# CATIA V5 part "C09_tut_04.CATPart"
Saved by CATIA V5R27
Part number: Part1
Bounding box of the stored display mesh (mm): x -112.5 to 112.5, y -202.5 to 80, z -202.5 to 85
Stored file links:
  E:\_Deepak\2017_Deepak\CATIA\Resources\Tutorial Files\Tutorials\c09_catia_v5_6r2016_tut\C09_tut_04.CATPart
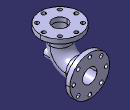
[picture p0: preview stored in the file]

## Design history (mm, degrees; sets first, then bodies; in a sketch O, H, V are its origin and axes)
Body1 (main body)
  Sketch1 on yz-plane, origin (0, 0, 0), H (0, 1, 0), V (0, 0, 1)
    line L1 (-90, 60) -> (-90, 0)
    point P1 (-90, 60)
    arc A1 centre (0, 0) radius 90 from (-90, 0) to (0, -90) ccw
    point P3 (0, 0)
    line L2 (0, -90) -> (55, -90)
    point P5 (55, -90)
    distance P1 L2 = 150
    distance P5 L1 = 145
    radius A1 = 90
    vertical: L1 V
    tangency: A1 L1, L2 A1
    horizontal: L2 H
    coincidence: P3 O
  Plane1: type Normal, Curve Sketch1, RefPoint Sketch1.P5, Ratio 0
  Sketch2 on Plane1, origin (0, 55, 0), H (-1, 0, 0), V (0, 0, 1)
    circle A1 centre (0, -90) radius 48.5
    point P1 (0, -90)
    reference projected point E1 (0, -90) from Sketch1.P5
    radius A1 = 48.5
    coincidence: P1 V, P1 E1
  Rib1: profile Sketch2, centre curve Sketch1, thin wall 16
  Sketch3 on face of Rib1, origin (0, 55, 0), H (-1, 0, 0), V (0, 0, 1)
    circle A1 centre (0, -90) radius 112.5
    point P1 (0, -90)
    reference projected circle E1 centre (0, -90) radius 56.5 from edge [face of Rib1 | face of Rib1]
    circle A2 centre (0, -90) radius 40.5
    reference projected circle E2 centre (0, -90) radius 40.5 from edge [face of Rib1 | face of Rib1]
    radius A1 = 112.5
    coincidence: P1 V, A2 E2
    concentricity: A1 E1
  Pad1: profile Sketch3, direction (0, 1, 0), length 25
  Sketch4 on face of Rib1, origin (0, 0, 60), H (1, 0, 0), V (0, 1, 0)
    circle A1 centre (0, -90) radius 112.5
    point P1 (0, -90)
    reference projected circle E1 centre (0, -90) radius 56.5 from edge [face of Rib1 | face of Rib1]
    circle A2 centre (0, -90) radius 40.5
    reference projected circle E2 centre (0, -90) radius 40.5 from edge [face of Rib1 | face of Rib1]
    radius A1 = 112.5
    coincidence: P1 V, A2 E2
    concentricity: A1 E1
  Pad2: profile Sketch4, direction (0, 0, 1), length 25
  Plane2: type Offset, RefPlane end face of Pad1, Offset 240
  Sketch5 on Plane2, origin (0, -160, 0), H (-1, 0, 0), V (0, 0, 1)
    circle A1 centre (0, -90) radius 25
    point P1 (0, -90)
    reference projected line E1 (-112.5, 85) -> (112.5, 85) from edge [face of Pad2 from Sketch4.A1 | end face of Pad2]
    radius A1 = 25
    distance E1 P1 = 175
    coincidence: P1 V
  Pad3: profile Sketch5, direction (0, 1, 0), up to the existing solid (limit type 2)
  Point1: type Center, Curve edge [start face of Pad3 | face of Pad3 from Sketch5.A1]
  Sketch6 on start face of Pad3, origin (0, -160, -90), H (1, 0, 0), V (0, 0, 1)
    point P1 (0, 0)
    reference projected point E1 (0, 0) from Point1
    coincidence: E1 P1
  Hole1: placed by Sketch6, at (0, -160, -90) direction (0, 1, 0), diameter 20, through (limit type 6), counterbore diameter 24, counterbore depth 28
  Sketch7 on end face of Pad1, origin (0, 80, 0), H (-1, 0, 0), V (0, 0, 1)
    construction circle A1 centre (0, -90) radius 92.5
    point P1 (0, -90)
    reference projected circle E1 centre (0, -90) radius 112.5 from edge [face of Pad1 from Sketch3.A1 | end face of Pad1]
    point P2 (0, 2.5)
    radius A1 = 92.5
    coincidence: P1 V, P2 A1, P2 V
    concentricity: A1 E1
  Sketch8 on end face of Pad1, origin (0, 80, 2.5), H (1, 0, 0), V (0, 0, -1)
    point P1 (0, 0)
    reference projected point E1 (0, 0) from Sketch7.P2
    coincidence: E1 P1
  Hole2: placed by Sketch8, at (0, 80, 2.5) direction (0, -1, 0), diameter 20.5, through (limit type 6)
  CircPattern1: of Hole2, instances 8, angular step 45 {= 360.0*1 deg/CircPattern1.AngularNumber}, axis from face of Pad1
  Sketch9 on end face of Pad2, origin (0, 0, 85), H (1, 0, 0), V (0, 1, 0)
    construction circle A1 centre (0, -90) radius 92.5
    point P1 (0, -90)
    reference projected circle E1 centre (0, -90) radius 112.5 from edge [face of Pad2 from Sketch4.A1 | end face of Pad2]
    point P2 (0, 2.5)
    radius A1 = 92.5
    coincidence: P1 V, P2 A1, P2 V
    concentricity: A1 E1
  Sketch10 on end face of Pad2, origin (0, 2.5, 85), H (1, 0, 0), V (0, 1, 0)
    point P1 (0, 0)
    reference projected point E1 (0, 0) from Sketch9.P2
    coincidence: E1 P1
  Hole3: placed by Sketch10, at (0, 2.5, 85) direction (0, 0, -1), diameter 20.5, through (limit type 6)
  CircPattern2: of Hole3, instances 8, angular step 45 {= 360.0*1 deg/CircPattern2.AngularNumber}, axis from face of Pad2 from Sketch4.A2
